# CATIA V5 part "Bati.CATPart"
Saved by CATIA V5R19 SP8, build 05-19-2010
Part number: Bati
Publications: "Entraxe_bati", "Diam_ext_bati", "Epaisseur_trou_bati"
Bounding box of the stored display mesh (mm): x 0 to 420, y 0 to 100, z -40 to 40
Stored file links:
  F:\! CONCEPTION\PROJET\Mécanisme 544\CAO\Bati.CATPart
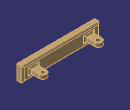
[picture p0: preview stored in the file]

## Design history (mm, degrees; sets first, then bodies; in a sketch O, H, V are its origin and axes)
Parameters
  Entraxe_bati = 300 mm
  Diam_ext_bati = 20 mm
  Epaisseur_trou_bati = 20 mm
Body1 (main body)
  Sketch1 on xy-plane, origin (0, 0, 0), H (1, 0, 0), V (0, 1, 0)
    point P1 (0, 0)
    line L1 (0, 0) -> (0, 20)
    arc A1 centre (10, 20) radius 10 from (0, 20) to (10, 30) cw
    line L2 (10, 30) -> (30, 30)
    arc A2 centre (30, 40) radius 10 from (30, 30) to (40, 40) ccw
    line L3 (40, 40) -> (40, 80)
    arc A3 centre (60, 80) radius 20 from (40, 80) to (80, 80) cw
    point P9 (60, 80)
    line L4 (80, 80) -> (80, 40)
    arc A4 centre (90, 40) radius 10 from (80, 40) to (90, 30) ccw
    line L5 (90, 30) -> (330, 30)
    arc A5 centre (330, 40) radius 10 from (330, 30) to (340, 40) ccw
    line L6 (340, 40) -> (340, 80)
    arc A6 centre (360, 80) radius 20 from (340, 80) to (380, 80) cw
    point P18 (360, 80)
    line L7 (380, 80) -> (380, 40)
    arc A7 centre (390, 40) radius 10 from (380, 40) to (390, 30) ccw
    line L8 (390, 30) -> (410, 30)
    arc A8 centre (410, 20) radius 10 from (410, 30) to (420, 20) cw
    line L9 (420, 20) -> (420, 0)
    point P26 (420, 0)
    line L10 (420, 0) -> (0, 0)
    radius A3 = 20 {= Diam_ext_bati}
    radius A6 = 20 {= Diam_ext_bati}
    distance L2 L10 = 30
    length L3 = 40
    length L2 = 20
    length L8 = 20
    distance P9 P18 = 300 {= Entraxe_bati}
    distance L5 L10 = 30
    radius A2 = 10
    radius A4 = 10
    radius A5 = 10
    radius A7 = 10
    radius A1 = 10
    radius A8 = 10
    length L7 = 40
    coincidence: P1 H, P26 H, L1 V
    vertical: L1 V, L9 V, L3 V, L4 V, L6 V, L7 V
    tangency: A1 L1, L2 A1, A2 L2, L3 A2, A3 L3, L4 A3, A4 L4, L5 A4, A5 L5, L6 A5, A6 L6, L7 A6, A7 L5, A7 L7, L8 A7, A8 L8, L9 A8
    horizontal: L10 H, L8 H, L5 H, L2 H
  Sketch2 on yz-plane, origin (0, 0, 0), H (0, 1, 0), V (0, 0, 1)
    point P1 (0, -40)
    line L1 (0, -40) -> (20, -40)
    arc A1 centre (20, -30) radius 10 from (20, -40) to (30, -30) ccw
    line L2 (30, -30) -> (30, -20)
    arc A2 centre (40, -20) radius 10 from (30, -20) to (40, -10) cw
    line L3 (40, -10) -> (100, -10)
    line L4 (100, -10) -> (100, 10)
    line L5 (100, 10) -> (40, 10)
    arc A3 centre (40, 20) radius 10 from (40, 10) to (30, 20) cw
    line L6 (30, 20) -> (30, 30)
    arc A4 centre (20, 30) radius 10 from (30, 30) to (20, 40) ccw
    line L7 (20, 40) -> (0, 40)
    point P16 (0, 40)
    line L8 (0, 40) -> (0, -40)
    reference projected point E1 (40, 0) from vertex [element of Sketch1 | element of Sketch1]
    reference projected point E2 (20, 0) from vertex [element of Sketch1 | element of Sketch1]
    radius A4 = 10
    radius A3 = 10
    radius A2 = 10
    radius A1 = 10
    distance L5 H = 10 {= Epaisseur_trou_bati /2}
    distance E1 L3 = 10 {= Epaisseur_trou_bati /2}
    distance E2 L1 = 40 {= 20mm + Epaisseur_trou_bati}
    distance H L7 = 40 {= 20mm + Epaisseur_trou_bati}
    distance L6 L8 = 30
    distance L8 L4 = 100 {= 80mm + Diam_ext_bati}
    coincidence: P1 V, P16 V
    horizontal: L1 H, L5 H, L7 H, L3 H
    tangency: A1 L1, L2 A1, A2 L2, L3 A2, A3 L2, A3 L5, L6 A3, A4 L6, L7 A4
    vertical: L4 V, L8 V, L2 V, L6 V
  SolidCombine1: FirstComponentProfile Sketch1, FirstComponentDirection Sketch1, SecondComponentProfile Sketch2, SecondComponentDirection Sketch2
  Sketch3 on face of SolidCombine1 from Sketch2.L5, origin (0, 100, 10), H (0, -1, 0), V (1, 0, 0)
    circle A1 centre (20, 360) radius 12.5
    point P1 (20, 360)
    circle A2 centre (20, 60) radius 12.5
    point P2 (20, 60)
    reference projected line E3 (100, 0) -> (100, 420) from edge [face of SolidCombine1 from Sketch2.L8 | face of SolidCombine1 from Sketch2.L7]
    reference projected line E4 (100, 0) -> (100, 420) from edge [face of SolidCombine1 from Sketch2.L8 | face of SolidCombine1 from Sketch2.L7]
    radius A2 = 12.5 {= (Diam_ext_bati+5mm)/2}
    radius A1 = 12.5 {= (Diam_ext_bati+5mm)/2}
    distance P2 P1 = 300 {= Entraxe_bati}
    distance P1 E3 = 80
    distance P2 E4 = 80
    distance P2 H = 60 {= 40mm + Diam_ext_bati}
  Pocket1: profile Sketch3, direction (0, 0, -1), through (limit type 3)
